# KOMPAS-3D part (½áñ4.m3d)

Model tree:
1. Эскиз:1
2. Операция выдавливания:1
     Расстояние 1 = 20
3. Эскиз:2
4. Операция выдавливания:2
     Расстояние 1 = 400
5. Эскиз:3
6. Вырезать элемент выдавливания:1
     Расстояние 1 = 70
7. Эскиз:4
8. Вырезать элемент выдавливания:2
     Расстояние 1 = 2
9. Эскиз:5
10. Эскиз:11
11. Вырезать элемент выдавливания:7
     Расстояние 1 = 30
12. Эскиз:12
13. Вырезать элемент выдавливания:8
     Расстояние 1 = 30
